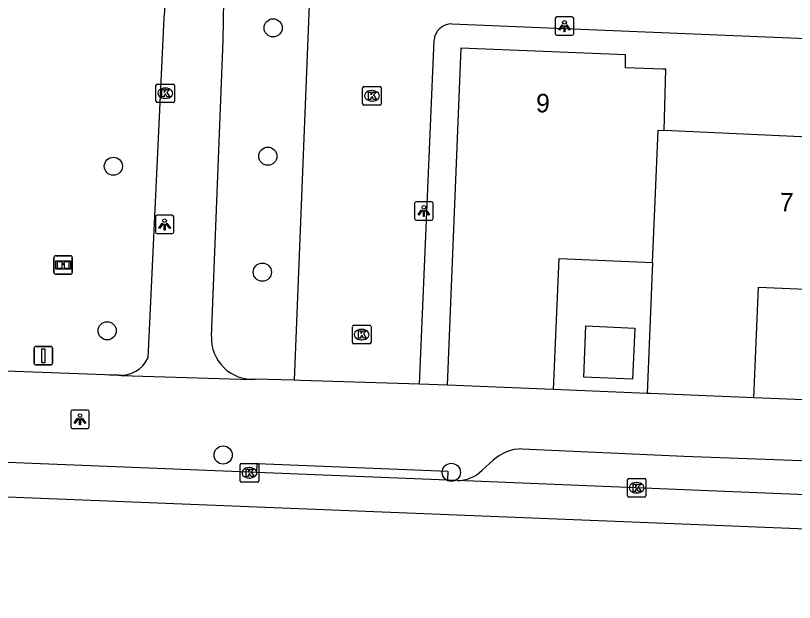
# Model space of a CAD drawing. Extents: x 160787 to 161428, y 386828 to 387483.
# Drawn here: x 161138.66 to 161180.65, y 386896.41 to 386928.07 of the extents above; entities that cross this region are included whole.
import ezdxf

# ---------------------------------------------------------------- set-up
doc = ezdxf.new("R2010")
doc.units = 0
for name, color, linetype in [('IMGEO_Boom', 7, 'Continuous'), ('IMGEO_Informatiebord', 7, 'Continuous'), ('IMGEO_Kolk', 7, 'Continuous'), ('IMGEO_Lichtpunt', 7, 'Continuous'), ('IMGEO_Pand', 7, 'Continuous'), ('IMGEO_Pand_nummerreeks', 7, 'Continuous'), ('IMGEO_Rijbaan_lokaal_gesloten', 7, 'Continuous'), ('IMGEO_Verkeersbordpaal', 7, 'Continuous'), ('IMGEO_Voetpad_open', 7, 'Continuous')]:
    doc.layers.add(name, color=color, linetype=linetype)

msp = doc.modelspace()

# ---------------------------------------------------------------- linework, layer by layer
at = {"layer": 'IMGEO_Boom'}
for centre in [(161152.545, 386927.404), (161152.26, 386920.481), (161143.933, 386919.94), (161151.963, 386914.227), (161143.598, 386911.064), (161149.849, 386904.364), (161162.153, 386903.429)]:
    msp.add_circle(centre, 0.489, dxfattribs=at)
at = {"layer": 'IMGEO_Informatiebord'}
for p, q in [((161140.727, 386914.212), (161140.727, 386915.012)), ((161140.727, 386915.012), (161140.727, 386914.212)), ((161140.827, 386915.112), (161141.617, 386915.112)), ((161141.617, 386915.112), (161140.827, 386915.112)), ((161141.717, 386915.012), (161141.717, 386914.212)), ((161141.717, 386914.212), (161141.717, 386915.012)), ((161141.617, 386914.112), (161140.827, 386914.112)), ((161140.827, 386914.112), (161141.617, 386914.112))]:
    msp.add_line(p, q, dxfattribs=at)
for points in [[(161140.828, 386914.844), (161141.616, 386914.844), (161141.616, 386914.38), (161140.828, 386914.38), (161140.828, 386914.844)], [(161140.893, 386914.779), (161140.893, 386914.445), (161141.168, 386914.445), (161141.169, 386914.658), (161141.273, 386914.659), (161141.274, 386914.445), (161141.551, 386914.445), (161141.551, 386914.779), (161141.275, 386914.779), (161141.275, 386914.699), (161141.169, 386914.699), (161141.169, 386914.779), (161140.893, 386914.779)]]:
    msp.add_lwpolyline(points, dxfattribs=at)
for centre, start, end in [((161140.827, 386915.012), 90, 180), ((161140.827, 386915.012), 90, 180), ((161141.617, 386915.012), 0, 90), ((161141.617, 386915.012), 360, 90), ((161140.827, 386914.212), 180, 270), ((161140.827, 386914.212), 180, 270), ((161141.617, 386914.212), 270, 0), ((161141.617, 386914.212), 270, 0)]:
    msp.add_arc(centre, 0.1, start, end, dxfattribs=at)
at = {"layer": 'IMGEO_Kolk'}
for p, q in [((161146.227, 386923.449), (161146.227, 386924.301)), ((161146.302, 386924.375), (161147.154, 386924.375)), ((161146.715, 386924.155), (161146.74, 386924.155)), ((161147.228, 386924.301), (161147.228, 386923.449)), ((161157.369, 386923.312), (161157.369, 386924.164)), ((161157.444, 386924.238), (161158.296, 386924.238)), ((161158.37, 386924.164), (161158.37, 386923.312)), ((161157.857, 386924.018), (161157.882, 386924.018)), ((161147.154, 386923.375), (161146.302, 386923.375)), ((161146.738, 386923.595), (161146.713, 386923.595)), ((161158.296, 386923.238), (161157.444, 386923.238)), ((161157.88, 386923.458), (161157.855, 386923.458)), ((161156.822, 386910.435), (161156.822, 386911.287)), ((161156.897, 386911.361), (161157.749, 386911.361)), ((161157.31, 386911.141), (161157.335, 386911.141)), ((161157.823, 386911.287), (161157.823, 386910.435)), ((161157.749, 386910.361), (161156.897, 386910.361)), ((161157.333, 386910.581), (161157.308, 386910.581)), ((161150.769, 386902.978), (161150.769, 386903.83)), ((161150.844, 386903.904), (161151.696, 386903.904)), ((161151.257, 386903.684), (161151.282, 386903.684)), ((161151.77, 386903.83), (161151.77, 386902.978)), ((161151.28, 386903.124), (161151.255, 386903.124)), ((161171.717, 386903.097), (161172.569, 386903.097)), ((161151.696, 386902.904), (161150.844, 386902.904)), ((161171.642, 386902.171), (161171.642, 386903.023)), ((161172.13, 386902.877), (161172.155, 386902.877)), ((161172.643, 386903.023), (161172.643, 386902.171)), ((161172.153, 386902.317), (161172.128, 386902.317)), ((161172.569, 386902.097), (161171.717, 386902.097))]:
    msp.add_line(p, q, dxfattribs=at)
for points in [[(161146.227, 386923.449), (161146.227, 386924.301)], [(161146.302, 386924.375), (161147.154, 386924.375)], [(161146.548, 386924.075), (161146.671, 386924.075), (161146.671, 386923.924), (161146.801, 386924.075), (161146.965, 386924.075), (161146.819, 386923.924), (161146.972, 386923.675), (161146.82, 386923.675), (161146.735, 386923.839), (161146.671, 386923.772), (161146.671, 386923.675), (161146.548, 386923.675), (161146.548, 386924.075)], [(161147.228, 386924.301), (161147.228, 386923.449)], [(161157.369, 386923.312), (161157.369, 386924.164)], [(161157.444, 386924.238), (161158.296, 386924.238)], [(161158.37, 386924.164), (161158.37, 386923.312)], [(161157.69, 386923.938), (161157.813, 386923.938), (161157.813, 386923.787), (161157.943, 386923.938), (161158.107, 386923.938), (161157.961, 386923.787), (161158.114, 386923.538), (161157.962, 386923.538), (161157.877, 386923.702), (161157.813, 386923.635), (161157.813, 386923.538), (161157.69, 386923.538), (161157.69, 386923.938)], [(161147.154, 386923.375), (161146.302, 386923.375)], [(161158.296, 386923.238), (161157.444, 386923.238)], [(161156.822, 386910.435), (161156.822, 386911.287)], [(161156.897, 386911.361), (161157.749, 386911.361)], [(161157.143, 386911.061), (161157.266, 386911.061), (161157.266, 386910.91), (161157.396, 386911.061), (161157.56, 386911.061), (161157.414, 386910.91), (161157.567, 386910.661), (161157.415, 386910.661), (161157.33, 386910.825), (161157.266, 386910.758), (161157.266, 386910.661), (161157.143, 386910.661), (161157.143, 386911.061)], [(161157.823, 386911.287), (161157.823, 386910.435)], [(161157.749, 386910.361), (161156.897, 386910.361)], [(161150.769, 386902.978), (161150.769, 386903.83)], [(161150.844, 386903.904), (161151.696, 386903.904)], [(161151.09, 386903.604), (161151.213, 386903.604), (161151.213, 386903.453), (161151.343, 386903.604), (161151.507, 386903.604), (161151.361, 386903.453), (161151.514, 386903.204), (161151.362, 386903.204), (161151.277, 386903.368), (161151.213, 386903.301), (161151.213, 386903.204), (161151.09, 386903.204), (161151.09, 386903.604)], [(161151.77, 386903.83), (161151.77, 386902.978)], [(161171.717, 386903.097), (161172.569, 386903.097)], [(161151.696, 386902.904), (161150.844, 386902.904)], [(161171.642, 386902.171), (161171.642, 386903.023)], [(161171.963, 386902.797), (161172.086, 386902.797), (161172.086, 386902.646), (161172.216, 386902.797), (161172.38, 386902.797), (161172.234, 386902.646), (161172.387, 386902.397), (161172.235, 386902.397), (161172.15, 386902.561), (161172.086, 386902.494), (161172.086, 386902.397), (161171.963, 386902.397), (161171.963, 386902.797)], [(161172.643, 386903.023), (161172.643, 386902.171)], [(161172.569, 386902.097), (161171.717, 386902.097)]]:
    msp.add_lwpolyline(points, dxfattribs=at)
for centre, start, end in [((161146.304, 386924.299), 91.552, 178.448), ((161146.304, 386924.299), 91.552, 178.448), ((161147.152, 386924.299), 1.552, 88.448), ((161147.152, 386924.299), 1.552, 88.448), ((161157.446, 386924.162), 91.552, 178.448), ((161157.446, 386924.162), 91.552, 178.448), ((161158.294, 386924.162), 1.552, 88.448), ((161158.294, 386924.162), 1.552, 88.448), ((161146.304, 386923.451), 181.552, 268.448), ((161146.304, 386923.451), 181.552, 268.448), ((161147.152, 386923.451), 271.552, 358.448), ((161147.152, 386923.451), 271.552, 358.448), ((161157.446, 386923.314), 181.552, 268.448), ((161157.446, 386923.314), 181.552, 268.448), ((161158.294, 386923.314), 271.552, 358.448), ((161158.294, 386923.314), 271.552, 358.448), ((161156.899, 386911.285), 91.552, 178.448), ((161156.899, 386911.285), 91.552, 178.448), ((161157.747, 386911.285), 1.552, 88.448), ((161157.747, 386911.285), 1.552, 88.448), ((161156.899, 386910.437), 181.552, 268.448), ((161156.899, 386910.437), 181.552, 268.448), ((161157.747, 386910.437), 271.552, 358.448), ((161157.747, 386910.437), 271.552, 358.448), ((161150.846, 386903.828), 91.552, 178.448), ((161150.846, 386903.828), 91.552, 178.448), ((161151.694, 386903.828), 1.552, 88.448), ((161151.694, 386903.828), 1.552, 88.448), ((161171.719, 386903.021), 91.552, 178.448), ((161171.719, 386903.021), 91.552, 178.448), ((161172.567, 386903.021), 1.552, 88.448), ((161172.567, 386903.021), 1.552, 88.448), ((161150.846, 386902.98), 181.552, 268.448), ((161150.846, 386902.98), 181.552, 268.448), ((161151.694, 386902.98), 271.552, 358.448), ((161151.694, 386902.98), 271.552, 358.448), ((161171.719, 386902.173), 181.552, 268.448), ((161171.719, 386902.173), 181.552, 268.448), ((161172.567, 386902.173), 271.552, 358.448), ((161172.567, 386902.173), 271.552, 358.448)]:
    msp.add_arc(centre, 0.0765, start, end, dxfattribs=at)
for centre, major_axis, ratio, start_param, end_param in [((161146.714, 386923.875), (-0.387, 0.002), 0.722429, 4.712389, 7.853982), ((161146.739, 386923.875), (-0.39, 0.002), 0.717154, 1.570796, 4.712389), ((161157.856, 386923.738), (-0.387, 0.002), 0.722429, 4.712389, 7.853982), ((161157.881, 386923.738), (-0.39, 0.002), 0.717154, 1.570796, 4.712389), ((161157.309, 386910.861), (-0.387, 0.002), 0.722429, 4.712389, 7.853982), ((161157.334, 386910.861), (-0.39, 0.002), 0.717154, 1.570796, 4.712389), ((161151.256, 386903.404), (-0.387, 0.002), 0.722429, 4.712389, 7.853982), ((161151.281, 386903.404), (-0.39, 0.002), 0.717154, 1.570796, 4.712389), ((161172.129, 386902.597), (-0.387, 0.002), 0.722429, 4.712389, 7.853982), ((161172.154, 386902.597), (-0.39, 0.002), 0.717154, 1.570796, 4.712389)]:
    msp.add_ellipse(centre, major_axis=major_axis, ratio=ratio, start_param=start_param, end_param=end_param, dxfattribs=at)
at = {"layer": 'IMGEO_Lichtpunt'}
for p, q in [((161167.755, 386927.904), (161167.755, 386927.097)), ((161167.755, 386927.904), (161167.755, 386927.097)), ((161168.657, 386927.999), (161167.849, 386927.999)), ((161168.657, 386927.999), (161167.849, 386927.999)), ((161168.751, 386927.097), (161168.751, 386927.904)), ((161168.751, 386927.097), (161168.751, 386927.904)), ((161167.849, 386927.003), (161168.657, 386927.003)), ((161167.849, 386927.003), (161168.657, 386927.003)), ((161160.173, 386917.931), (161160.173, 386917.124)), ((161160.173, 386917.931), (161160.173, 386917.124)), ((161161.075, 386918.026), (161160.267, 386918.026)), ((161161.075, 386918.026), (161160.267, 386918.026)), ((161161.169, 386917.124), (161161.169, 386917.931)), ((161161.169, 386917.124), (161161.169, 386917.931)), ((161146.195, 386917.206), (161146.195, 386916.399)), ((161146.195, 386917.206), (161146.195, 386916.399)), ((161147.097, 386917.301), (161146.289, 386917.301)), ((161147.097, 386917.301), (161146.289, 386917.301)), ((161147.191, 386916.399), (161147.191, 386917.206)), ((161147.191, 386916.399), (161147.191, 386917.206)), ((161160.267, 386917.03), (161161.075, 386917.03)), ((161160.267, 386917.03), (161161.075, 386917.03)), ((161146.289, 386916.305), (161147.097, 386916.305)), ((161146.289, 386916.305), (161147.097, 386916.305)), ((161141.632, 386906.694), (161141.632, 386905.887)), ((161141.632, 386906.694), (161141.632, 386905.887)), ((161142.534, 386906.789), (161141.726, 386906.789)), ((161142.534, 386906.789), (161141.726, 386906.789)), ((161142.628, 386905.887), (161142.628, 386906.694)), ((161142.628, 386905.887), (161142.628, 386906.694)), ((161141.726, 386905.793), (161142.534, 386905.793)), ((161141.726, 386905.793), (161142.534, 386905.793))]:
    msp.add_line(p, q, dxfattribs=at)
for points in [[(161168.129, 386927.568), (161168.168, 386927.54), (161167.98, 386927.278), (161167.942, 386927.305), (161168.129, 386927.568)], [(161168.231, 386927.52), (161168.278, 386927.52), (161168.278, 386927.198), (161168.231, 386927.198), (161168.231, 386927.52)], [(161168.341, 386927.54), (161168.379, 386927.567), (161168.566, 386927.305), (161168.527, 386927.277), (161168.341, 386927.54)], [(161160.547, 386917.595), (161160.586, 386917.567), (161160.398, 386917.305), (161160.36, 386917.332), (161160.547, 386917.595)], [(161160.649, 386917.547), (161160.696, 386917.547), (161160.696, 386917.225), (161160.649, 386917.225), (161160.649, 386917.547)], [(161160.759, 386917.567), (161160.797, 386917.594), (161160.984, 386917.332), (161160.945, 386917.304), (161160.759, 386917.567)], [(161146.569, 386916.87), (161146.608, 386916.842), (161146.42, 386916.58), (161146.382, 386916.607), (161146.569, 386916.87)], [(161146.671, 386916.822), (161146.718, 386916.822), (161146.718, 386916.5), (161146.671, 386916.5), (161146.671, 386916.822)], [(161146.781, 386916.842), (161146.819, 386916.869), (161147.006, 386916.607), (161146.967, 386916.579), (161146.781, 386916.842)], [(161142.006, 386906.358), (161142.045, 386906.33), (161141.857, 386906.068), (161141.819, 386906.095), (161142.006, 386906.358)], [(161142.108, 386906.31), (161142.155, 386906.31), (161142.155, 386905.988), (161142.108, 386905.988), (161142.108, 386906.31)], [(161142.218, 386906.33), (161142.256, 386906.357), (161142.443, 386906.095), (161142.404, 386906.067), (161142.218, 386906.33)]]:
    msp.add_lwpolyline(points, dxfattribs=at)
for centre in [(161168.254, 386927.702), (161160.672, 386917.729), (161146.694, 386917.004), (161142.131, 386906.492)]:
    msp.add_circle(centre, 0.0994, dxfattribs=at)
for centre, start, end in [((161167.849, 386927.904), 90, 180), ((161167.849, 386927.904), 90, 180), ((161168.657, 386927.904), 0, 90), ((161168.657, 386927.904), 0, 90), ((161167.849, 386927.097), 180, 270), ((161167.849, 386927.097), 180, 270), ((161168.657, 386927.097), 270, 0), ((161168.657, 386927.097), 270, 360), ((161160.267, 386917.931), 90, 180), ((161160.267, 386917.931), 90, 180), ((161161.075, 386917.931), 0, 90), ((161161.075, 386917.931), 0, 90), ((161146.289, 386917.206), 90, 180), ((161146.289, 386917.206), 90, 180), ((161147.097, 386917.206), 0, 90), ((161147.097, 386917.206), 0, 90), ((161160.267, 386917.124), 180, 270), ((161160.267, 386917.124), 180, 270), ((161161.075, 386917.124), 270, 0), ((161161.075, 386917.124), 270, 360), ((161146.289, 386916.399), 180, 270), ((161146.289, 386916.399), 180, 270), ((161147.097, 386916.399), 270, 0), ((161147.097, 386916.399), 270, 360), ((161141.726, 386906.694), 90, 180), ((161141.726, 386906.694), 90, 180), ((161142.534, 386906.694), 0, 90), ((161142.534, 386906.694), 0, 90), ((161141.726, 386905.887), 180, 270), ((161141.726, 386905.887), 180, 270), ((161142.534, 386905.887), 270, 0), ((161142.534, 386905.887), 270, 360)]:
    msp.add_arc(centre, 0.0946, start, end, dxfattribs=at)
at = {"layer": 'IMGEO_Pand'}
for points in [[(161173.621, 386921.87), (161173.723, 386925.173), (161173.553, 386925.179), (161171.547, 386925.252), (161171.545, 386925.944), (161162.673, 386926.31), (161161.921, 386908.14)], [(161173.005, 386914.747), (161173.128, 386917.649), (161173.307, 386921.885), (161173.621, 386921.87)], [(161187.022, 386920.605), (161182.164, 386920.731), (161182.182, 386921.468), (161173.621, 386921.87)], [(161167.669, 386907.897), (161167.968, 386914.96), (161173.005, 386914.747)], [(161173.005, 386914.747), (161172.707, 386907.686)], [(161178.458, 386907.447), (161178.706, 386913.412), (161186.74, 386913.083)], [(161169.295, 386908.559), (161169.412, 386911.326), (161172.044, 386911.215), (161171.927, 386908.448), (161169.295, 386908.559)], [(161167.669, 386907.897), (161161.921, 386908.14)], [(161178.458, 386907.447), (161172.881, 386907.679), (161172.707, 386907.686)]]:
    msp.add_lwpolyline(points, dxfattribs=at)
at = {"layer": 'IMGEO_Rijbaan_lokaal_gesloten'}
for points in [[(161151.67, 386903.416), (161135.502, 386904.066), (161131.97, 386904.208), (161128.825, 386904.334), (161123.496, 386904.504)], [(161161.944, 386903.003), (161151.67, 386903.416)], [(161280.349, 386896.413), (161248.174, 386897.682), (161123.39, 386902.685)], [(161162.46, 386902.982), (161161.944, 386903.003)], [(161223.699, 386900.466), (161162.46, 386902.982)]]:
    msp.add_lwpolyline(points, dxfattribs=at)
at = {"layer": 'IMGEO_Verkeersbordpaal'}
for p, q in [((161139.761, 386910.22), (161140.551, 386910.22)), ((161140.551, 386910.22), (161139.761, 386910.22)), ((161139.661, 386909.32), (161139.661, 386910.12)), ((161139.661, 386910.12), (161139.661, 386909.32)), ((161140.651, 386910.12), (161140.651, 386909.32)), ((161140.651, 386909.32), (161140.651, 386910.12)), ((161140.551, 386909.22), (161139.761, 386909.22)), ((161139.761, 386909.22), (161140.551, 386909.22))]:
    msp.add_line(p, q, dxfattribs=at)
msp.add_lwpolyline([(161140.081, 386910.095), (161140.231, 386910.095), (161140.231, 386909.345), (161140.081, 386909.345), (161140.081, 386910.095)], dxfattribs=at)
for centre, start, end in [((161139.761, 386910.12), 90, 180), ((161139.761, 386910.12), 90, 180), ((161140.551, 386910.12), 0, 90), ((161140.551, 386910.12), 360, 90), ((161139.761, 386909.32), 180, 270), ((161139.761, 386909.32), 180, 270), ((161140.551, 386909.32), 270, 0), ((161140.551, 386909.32), 270, 0)]:
    msp.add_arc(centre, 0.1, start, end, dxfattribs=at)
at = {"layer": 'IMGEO_Voetpad_open'}
for points in [[(161149.217, 386910.758), (161149.85, 386926.73), (161149.923, 386931.048)], [(161154.583, 386930.916), (161153.688, 386908.393)], [(161146.697, 386928.766), (161146.684, 386928.299), (161146.658, 386927.946), (161145.787, 386909.589)], [(161162.187, 386927.617), (161226.501, 386924.954)], [(161160.441, 386908.186), (161161.223, 386926.739)], [(161144.206, 386908.675), (161143.967, 386908.672), (161143.729, 386908.68), (161143.492, 386908.694), (161122.06, 386909.472)], [(161144.206, 386908.675), (161144.348, 386908.66), (161151.389, 386908.43), (161151.569, 386908.451)], [(161153.688, 386908.393), (161151.569, 386908.451)], [(161160.441, 386908.186), (161154.016, 386908.384), (161153.688, 386908.393)], [(161161.921, 386908.14), (161160.441, 386908.186)], [(161172.707, 386907.686), (161167.669, 386907.897)], [(161186.492, 386907.118), (161178.458, 386907.447)], [(161165.97, 386904.699), (161174.681, 386904.304), (161192.762, 386903.644), (161221.57, 386902.335)], [(161151.67, 386903.416), (161151.69, 386903.915), (161161.964, 386903.502), (161161.944, 386903.003)], [(161163.81, 386903.544), (161164.413, 386904.08)]]:
    msp.add_lwpolyline(points, dxfattribs=at)
for centre, radius, start, end in [((161162.168, 386926.669), 0.948, 88.875, 175.7788), ((161151.44, 386910.672), 2.225, 177.7862, 273.3206), ((161144.343, 386910.263), 1.594, 265.0762, 334.9895), ((161166.013, 386902.324), 2.376, 91.0327, 132.3288), ((161162.471, 386904.858), 1.876, 269.6575, 315.546)]:
    msp.add_arc(centre, radius, start, end, dxfattribs=at)

# ---------------------------------------------------------------- texts
at = {"layer": 'IMGEO_Pand_nummerreeks'}
for s, rotation, p in [('9', 357.6394, (161166.698, 386922.861)), ('7', 358.516, (161179.846, 386917.51))]:
    msp.add_text(s, height=1, rotation=rotation, dxfattribs=at).set_placement(p)

doc.saveas('drawing.dxf')
